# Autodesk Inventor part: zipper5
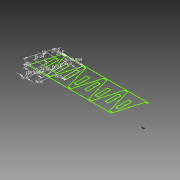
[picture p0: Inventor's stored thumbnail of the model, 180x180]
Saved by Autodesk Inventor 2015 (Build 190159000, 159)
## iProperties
Created: 2015-02
Part Number: zipper5
Material: Generic
Document SubType Name: Modeling
Designer: sungeun
Density: 1 g/cm^3
Appearance: Default
Author: sungeun
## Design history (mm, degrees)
sketch "Sketch1"
  geometry: L1 (0, 2)-(13.782, 50.063); L2 (13.782, 50.063)-(19.782, 50.063); L3 (19.782, 50.063)-(33.564, 2); L4 (33.564, 2)-(39.564, 2); L5 (39.564, 0)-(0, 0); L6 (13.782, 52.063)-(59.346, 52.063); L7 (59.346, 50.063)-(53.346, 50.063); L8 (53.346, 50.063)-(39.564, 2); L9 (13.782, 52.063)-(13.782, 50.063); L10 (0, 2)-(0, 0); L11 (210.186, 7.284)-(215.439, 7.284); L12 (215.439, 7.284)-(215.439, 3.639); L13 (215.439, 3.639)-(210.186, 3.639); L14 (210.186, 3.639)-(210.186, 7.284); L15 (13.782, 38.032)-(19.782, 38.032); L16 (19.782, 38.032)-(19.782, 14.032); L17 (19.782, 14.032)-(13.782, 14.032); L18 (13.782, 14.032)-(13.782, 38.032); L19 (33.564, 38.032)-(39.564, 38.032); L20 (39.564, 38.032)-(39.564, 14.032); L21 (39.564, 14.032)-(33.564, 14.032); L22 (33.564, 14.032)-(33.564, 38.032); L23 (53.346, 52.063)-(98.909, 52.063); L24 (53.346, 50.063)-(59.346, 50.063); L25 (39.564, 2)-(53.346, 50.063); L26 (59.346, 50.063)-(73.127, 2); L27 (53.346, 38.032)-(59.346, 38.032); L28 (59.346, 38.032)-(59.346, 14.032); L29 (53.346, 14.032)-(53.346, 38.032); L30 (59.346, 14.032)-(53.346, 14.032); L31 (79.127, 0)-(39.564, 0); L32 (73.127, 2)-(79.127, 2); L33 (79.127, 14.032)-(73.127, 14.032); L34 (79.127, 38.032)-(79.127, 14.032); L35 (73.127, 14.032)-(73.127, 38.032); L36 (73.127, 38.032)-(79.127, 38.032); L37 (92.909, 50.063)-(79.127, 2); L38 (98.909, 50.063)-(92.909, 50.063); L39 (92.909, 52.063)-(138.473, 52.063); L40 (92.909, 50.063)-(98.909, 50.063); L41 (79.127, 2)-(92.909, 50.063); L42 (98.909, 50.063)-(112.691, 2); L43 (92.909, 38.032)-(98.909, 38.032); L44 (98.909, 38.032)-(98.909, 14.032); L45 (92.909, 14.032)-(92.909, 38.032); L46 (98.909, 14.032)-(92.909, 14.032); L47 (118.691, 0)-(79.127, 0); L48 (112.691, 2)-(118.691, 2); L49 (118.691, 14.032)-(112.691, 14.032); L50 (118.691, 38.032)-(118.691, 14.032); L51 (112.691, 14.032)-(112.691, 38.032); L52 (112.691, 38.032)-(118.691, 38.032); L53 (132.473, 50.063)-(118.691, 2); L54 (138.473, 50.063)-(132.473, 50.063); L55 (132.473, 52.063)-(178.037, 52.063); L56 (132.473, 50.063)-(138.473, 50.063); L57 (118.691, 2)-(132.473, 50.063); L58 (138.473, 50.063)-(152.255, 2); L59 (132.473, 38.032)-(138.473, 38.032); L60 (138.473, 38.032)-(138.473, 14.032); L61 (132.473, 14.032)-(132.473, 38.032); L62 (138.473, 14.032)-(132.473, 14.032); L63 (158.255, 0)-(118.691, 0); L64 (152.255, 2)-(158.255, 2)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; 33 further points
  constraints: 132 end point, 8 midpoint, 6 parallel, 4 horizontal, 3 horizontal alignment, 3 perpendicular, 2 equal length, 2 vertical alignment, 1 collinear, 130 other
  dimensions: "d0" = 2 distance of L5.end L1.start; "d1" = 6 distance of L1.end L2.end; "d2" = 74 deg angle of L5 L1; "d4" = 2 distance between parallel lines of L5 L4 (= d0); "d14" = 2 distance of L1.end L6.start (= d4); "d17" = 2 distance between parallel lines of L6 L7 (= d0); "d18" = 6 distance of L7.start L7.end (= d1); "d34" = 6 distance of L3.end L4.end (= d1); "d35" = 33.56374 distance of L1.start L3.end (derived); "d36" = 50 distance of L1.start L1.end; "d44" = 6 distance of L16.end L17.end (= d1); "d45" = 24 distance of L17.end L15.start (= 4 x d1); "d46" = 6 distance of L20.end L21.end (= d1); "d47" = 24 distance of L21.end L19.start (= d45); "d50" = 39.56374 distance of L6.start L23.start (= d35 + d1)
other parameters: "d6" = 56.39702 (derived)
